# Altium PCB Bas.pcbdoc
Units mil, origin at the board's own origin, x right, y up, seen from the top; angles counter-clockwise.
Board outline 2425 x 2966 mil, 2 copper layers (Top Layer, Bottom Layer), stack 62.2 mil thick; 43 components, 38 nets, 146 pads, 58 vias.
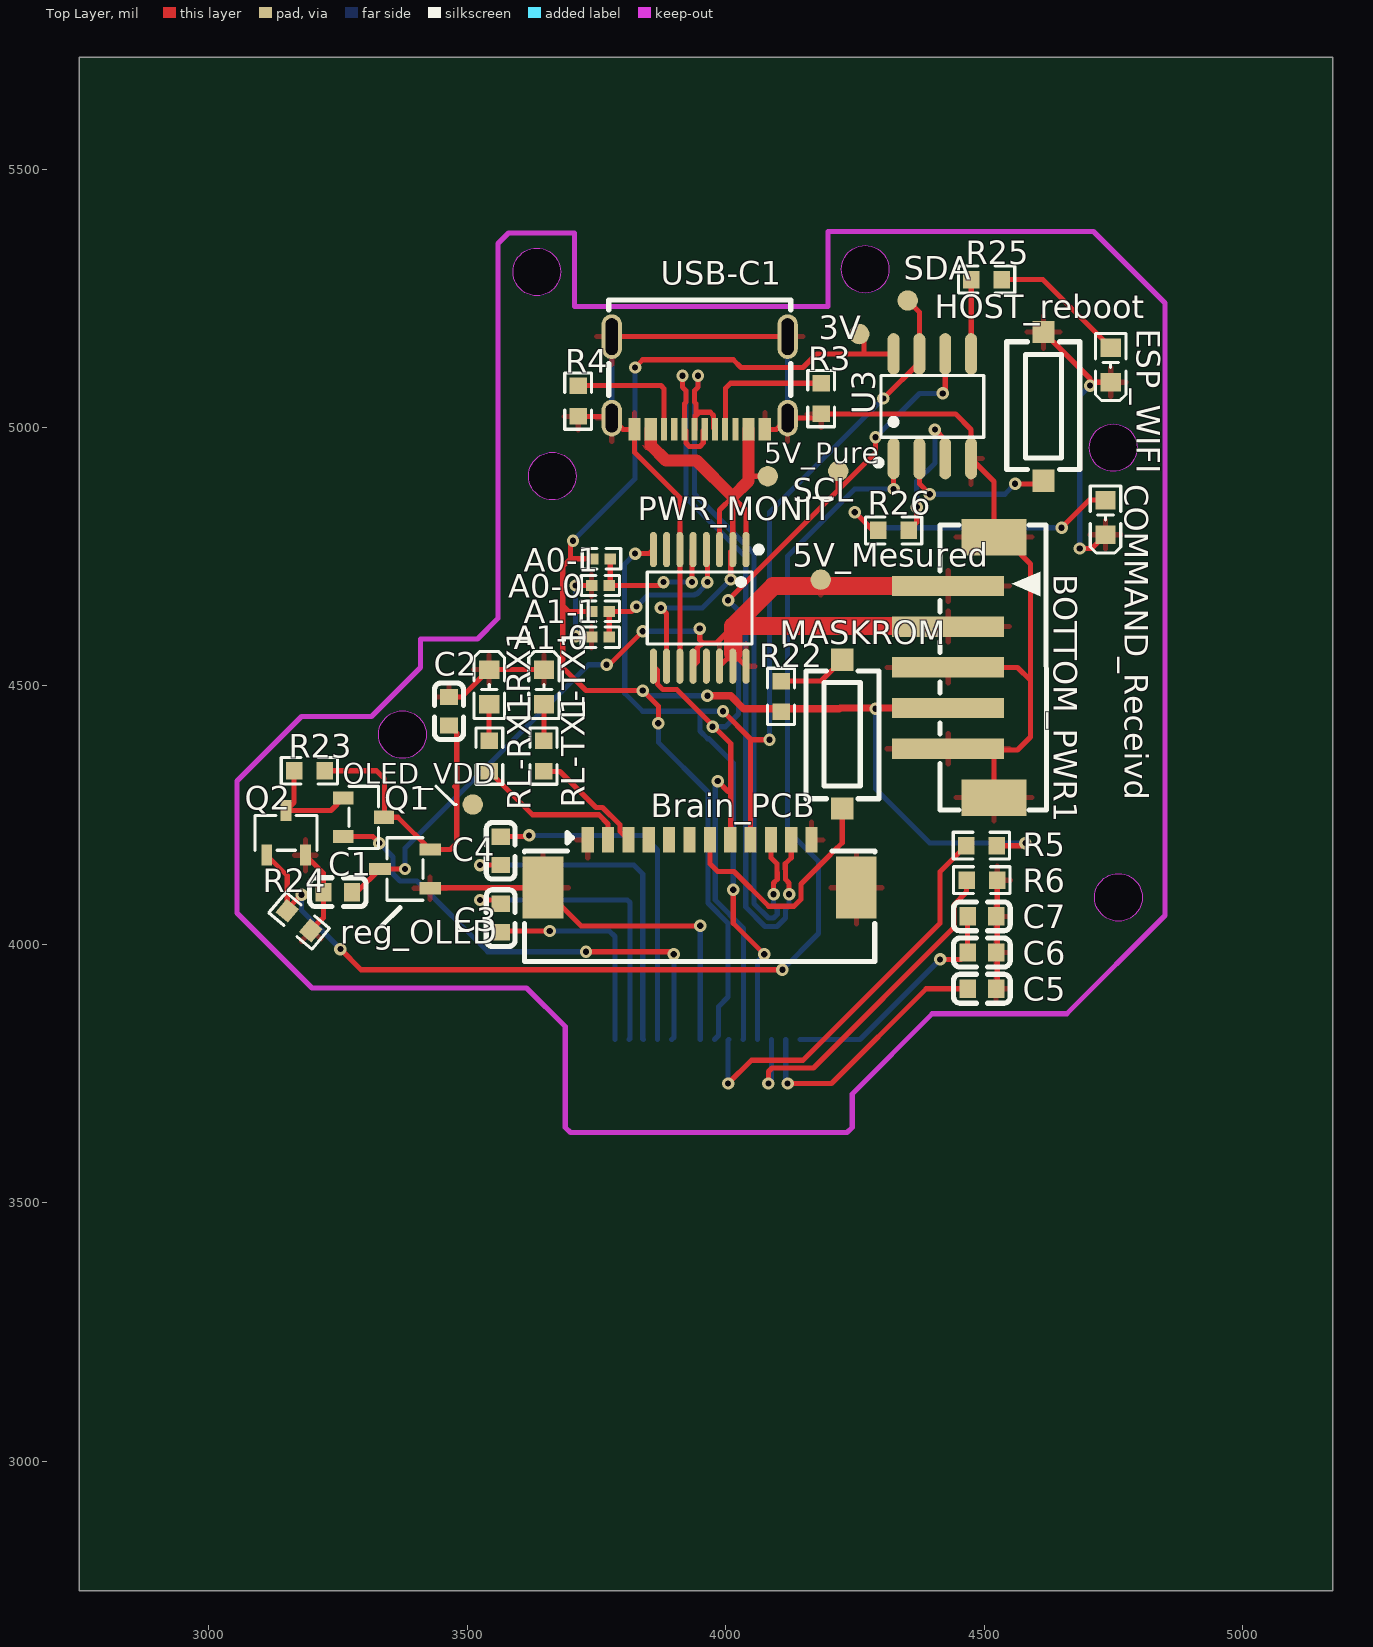
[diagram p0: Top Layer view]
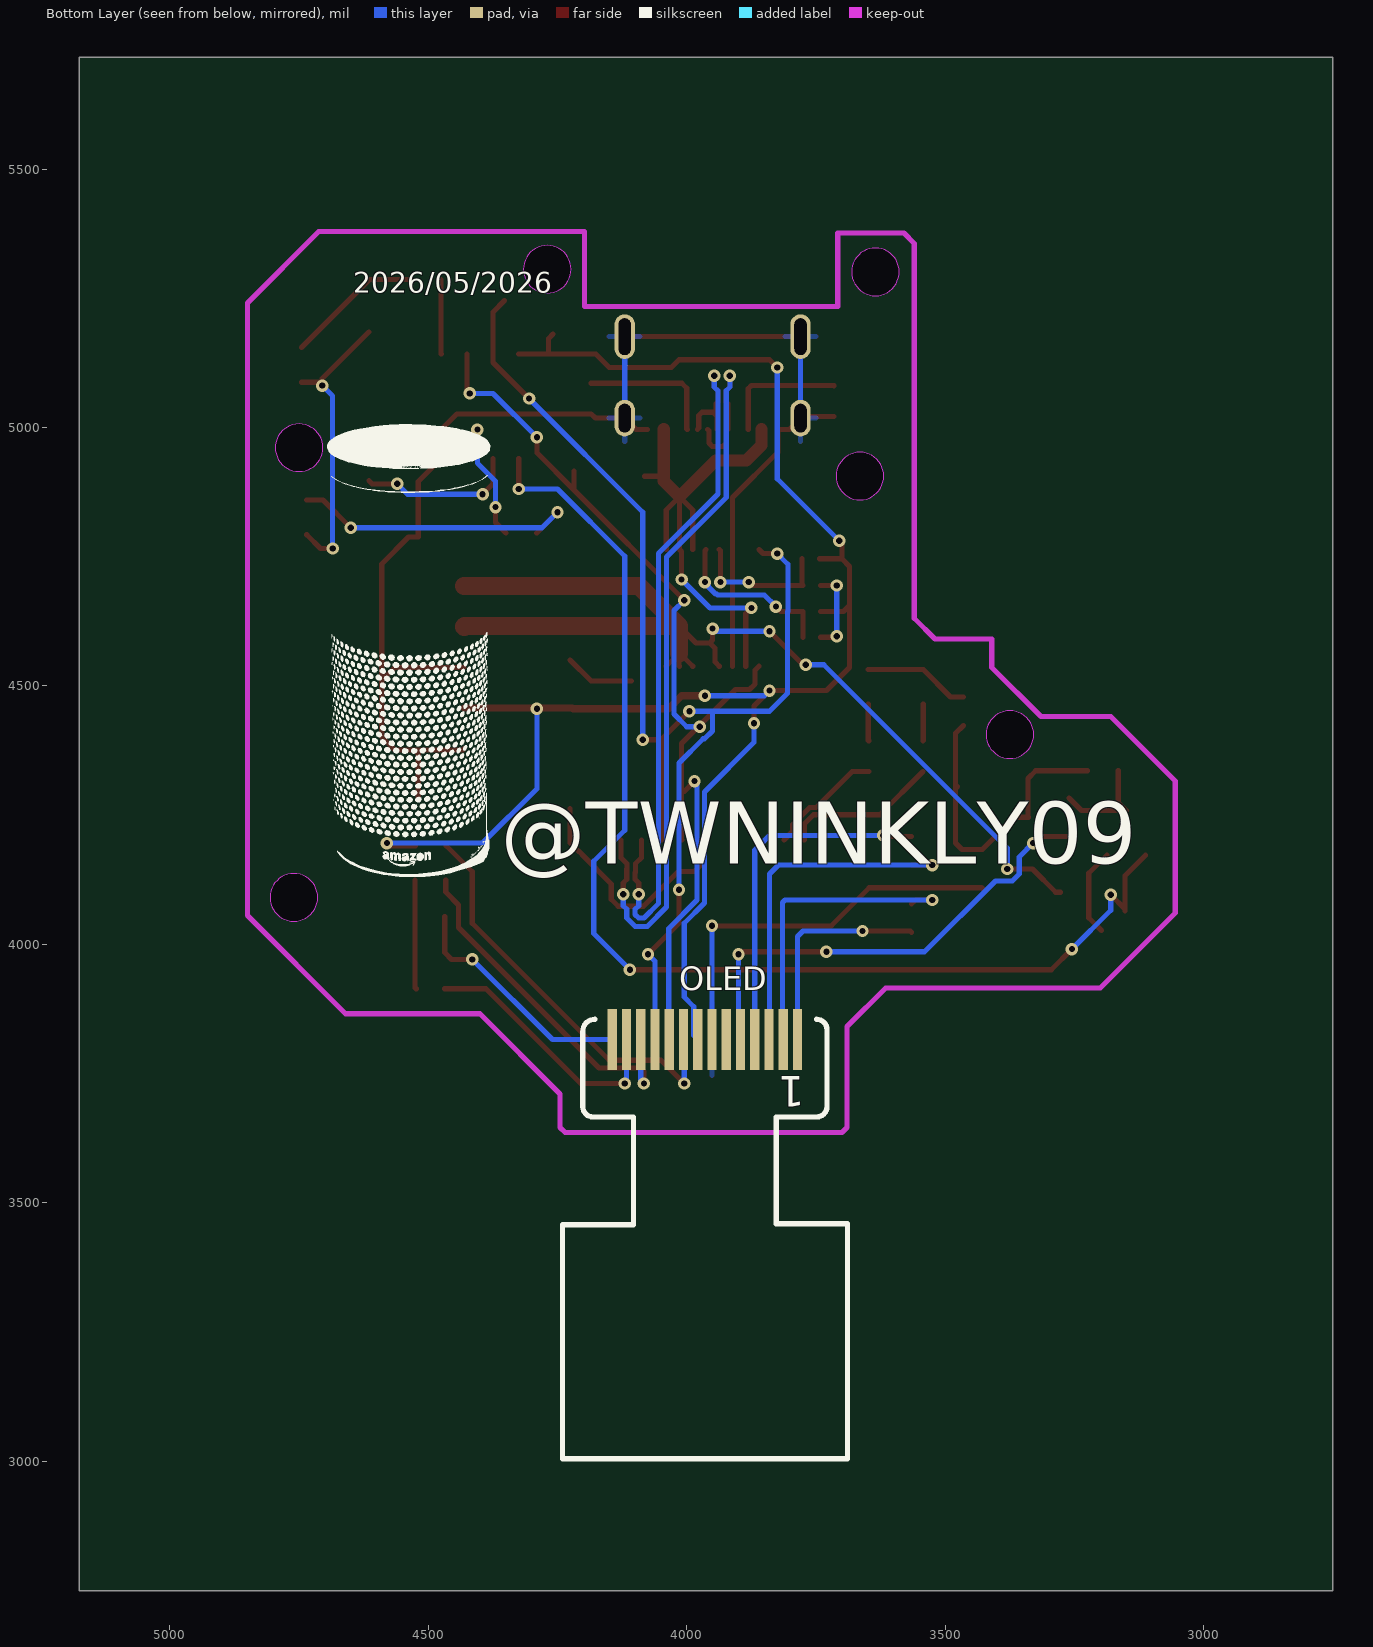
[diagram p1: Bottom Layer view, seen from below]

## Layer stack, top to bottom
Top Solder Mask Layer: solder mask 0.4, Dk 3.3
Top Layer: signal copper 1.4
Dielectric1: surface 59.4, FR4, Dk 4.5
Bottom Layer: signal copper 1.4
Bottom Solder Mask Layer: solder mask 0.4, Dk 3.3

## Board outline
5175,2750 2750,2750 2750,5716 5175,5716
cut-out: 3711.1,4906 3710.7,4900 3709.5,4894.1 3707.6,4888.4 3704.9,4883 3701.6,4878 3697.6,4873.4 3693.1,4869.5 3688,4866.1 3682.6,4863.4 3676.9,4861.5 3671,4860.3 3665,4859.9 3659,4860.3 3653.1,4861.5 3647.4,4863.4 3642,4866.1 3636.9,4869.5 3632.4,4873.4 3628.4,4878 3625.1,4883 3622.4,4888.4 3620.5,4894.1 3619.3,4900 3618.9,4906 3619.3,4912 3620.5,4918 3622.4,4923.7 3625.1,4929.1 3628.4,4934.1 3632.4,4938.6 3636.9,4942.6 3642,4945.9 3647.4,4948.6 3653.1,4950.5 3659,4951.7 3665,4952.1 3671,4951.7 3676.9,4950.5 3682.6,4948.6 3688,4945.9 3693.1,4942.6 3697.6,4938.6 3701.6,4934.1 3704.9,4929.1 3707.6,4923.7 3709.5,4918 3710.7,4912
cut-out: 3681.1,5301 3680.7,5295 3679.5,5289.1 3677.6,5283.4 3674.9,5278 3671.6,5273 3667.6,5268.4 3663.1,5264.5 3658,5261.1 3652.6,5258.4 3646.9,5256.5 3641,5255.3 3635,5254.9 3629,5255.3 3623.1,5256.5 3617.4,5258.4 3612,5261.1 3606.9,5264.5 3602.4,5268.4 3598.4,5273 3595.1,5278 3592.4,5283.4 3590.5,5289.1 3589.3,5295 3588.9,5301 3589.3,5307 3590.5,5313 3592.4,5318.7 3595.1,5324.1 3598.4,5329.1 3602.4,5333.6 3606.9,5337.6 3612,5340.9 3617.4,5343.6 3623.1,5345.5 3629,5346.7 3635,5347.1 3641,5346.7 3646.9,5345.5 3652.6,5343.6 3658,5340.9 3663.1,5337.6 3667.6,5333.6 3671.6,5329.1 3674.9,5324.1 3677.6,5318.7 3679.5,5313 3680.7,5307
cut-out: 4316.1,5306 4315.7,5300 4314.5,5294.1 4312.6,5288.4 4309.9,5283 4306.6,5278 4302.6,5273.4 4298.1,5269.5 4293,5266.1 4287.6,5263.4 4281.9,5261.5 4276,5260.3 4270,5259.9 4264,5260.3 4258.1,5261.5 4252.4,5263.4 4247,5266.1 4241.9,5269.5 4237.4,5273.4 4233.4,5278 4230.1,5283 4227.4,5288.4 4225.5,5294.1 4224.3,5300 4223.9,5306 4224.3,5312 4225.5,5318 4227.4,5323.7 4230.1,5329.1 4233.4,5334.1 4237.4,5338.6 4241.9,5342.6 4247,5345.9 4252.4,5348.6 4258.1,5350.5 4264,5351.7 4270,5352.1 4276,5351.7 4281.9,5350.5 4287.6,5348.6 4293,5345.9 4298.1,5342.6 4302.6,5338.6 4306.6,5334.1 4309.9,5329.1 4312.6,5323.7 4314.5,5318 4315.7,5312
cut-out: 4796.1,4961 4795.7,4955 4794.5,4949.1 4792.6,4943.4 4789.9,4938 4786.6,4933 4782.6,4928.4 4778.1,4924.5 4773,4921.1 4767.6,4918.4 4761.9,4916.5 4756,4915.3 4750,4914.9 4744,4915.3 4738.1,4916.5 4732.4,4918.4 4727,4921.1 4721.9,4924.5 4717.4,4928.4 4713.4,4933 4710.1,4938 4707.4,4943.4 4705.5,4949.1 4704.3,4955 4703.9,4961 4704.3,4967 4705.5,4973 4707.4,4978.7 4710.1,4984.1 4713.4,4989.1 4717.4,4993.6 4721.9,4997.6 4727,5000.9 4732.4,5003.6 4738.1,5005.5 4744,5006.7 4750,5007.1 4756,5006.7 4761.9,5005.5 4767.6,5003.6 4773,5000.9 4778.1,4997.6 4782.6,4993.6 4786.6,4989.1 4789.9,4984.1 4792.6,4978.7 4794.5,4973 4795.7,4967
cut-out: 4806.1,4091 4805.7,4085 4804.5,4079.1 4802.6,4073.4 4799.9,4068 4796.6,4063 4792.6,4058.4 4788.1,4054.5 4783,4051.1 4777.6,4048.4 4771.9,4046.5 4766,4045.3 4760,4044.9 4754,4045.3 4748.1,4046.5 4742.4,4048.4 4737,4051.1 4731.9,4054.5 4727.4,4058.4 4723.4,4063 4720.1,4068 4717.4,4073.4 4715.5,4079.1 4714.3,4085 4713.9,4091 4714.3,4097 4715.5,4103 4717.4,4108.7 4720.1,4114.1 4723.4,4119.1 4727.4,4123.6 4731.9,4127.6 4737,4130.9 4742.4,4133.6 4748.1,4135.5 4754,4136.7 4760,4137.1 4766,4136.7 4771.9,4135.5 4777.6,4133.6 4783,4130.9 4788.1,4127.6 4792.6,4123.6 4796.6,4119.1 4799.9,4114.1 4802.6,4108.7 4804.5,4103 4805.7,4097
cut-out: 3421.1,4406 3420.7,4400 3419.5,4394.1 3417.6,4388.4 3414.9,4383 3411.6,4378 3407.6,4373.4 3403.1,4369.5 3398,4366.1 3392.6,4363.4 3386.9,4361.5 3381,4360.3 3375,4359.9 3369,4360.3 3363.1,4361.5 3357.4,4363.4 3352,4366.1 3346.9,4369.5 3342.4,4373.4 3338.4,4378 3335.1,4383 3332.4,4388.4 3330.5,4394.1 3329.3,4400 3328.9,4406 3329.3,4412 3330.5,4418 3332.4,4423.7 3335.1,4429.1 3338.4,4434.1 3342.4,4438.6 3346.9,4442.6 3352,4445.9 3357.4,4448.6 3363.1,4450.5 3369,4451.7 3375,4452.1 3381,4451.7 3386.9,4450.5 3392.6,4448.6 3398,4445.9 3403.1,4442.6 3407.6,4438.6 3411.6,4434.1 3414.9,4429.1 3417.6,4423.7 3419.5,4418 3420.7,4412

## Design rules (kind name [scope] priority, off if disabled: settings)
BoardOutlineClearance copperThickness1oz [All] p0: genericclearance=10 ignorepadtopadclearanceinfootprint=FALSE except(0: Arc-SplitContinuation Track-SplitContinuation SMDPad-SplitContinuation THPad-SplitContinuation Via-SplitContinuation Fill-SplitContinuation Poly-SplitContinuation Region-SplitContinuation Text-SplitContinuation)
BoardOutlineClearance copperThickness2oz [All] p0: genericclearance=10 ignorepadtopadclearanceinfootprint=FALSE except(0: Arc-SplitContinuation Track-SplitContinuation SMDPad-SplitContinuation THPad-SplitContinuation Via-SplitContinuation Fill-SplitContinuation Poly-SplitContinuation Region-SplitContinuation Text-SplitContinuation)
BoardOutlineClearance Plane_innerPlane [All] p0: genericclearance=10 ignorepadtopadclearanceinfootprint=FALSE except(0: Arc-SplitContinuation Track-SplitContinuation SMDPad-SplitContinuation THPad-SplitContinuation Via-SplitContinuation Fill-SplitContinuation Poly-SplitContinuation Region-SplitContinuation Text-SplitContinuation)
BoardOutlineClearance Copper_copperRegion [All] p0: genericclearance=10 ignorepadtopadclearanceinfootprint=FALSE except(0: Arc-SplitContinuation Track-SplitContinuation SMDPad-SplitContinuation THPad-SplitContinuation Via-SplitContinuation Fill-SplitContinuation Poly-SplitContinuation Region-SplitContinuation Text-SplitContinuation)
BoardOutlineClearance otherClearance [All] p0: genericclearance=10 ignorepadtopadclearanceinfootprint=FALSE except(0: Arc-SplitContinuation Track-SplitContinuation SMDPad-SplitContinuation THPad-SplitContinuation Via-SplitContinuation Fill-SplitContinuation Poly-SplitContinuation Region-SplitContinuation Text-SplitContinuation)
Clearance copperThickness1oz [All] p1: gap=7 ignorepadtopadclearanceinfootprint=FALSE
Clearance copperThickness2oz [All] p1: gap=7 ignorepadtopadclearanceinfootprint=FALSE
Clearance Plane_innerPlane [All] p1: gap=7 ignorepadtopadclearanceinfootprint=FALSE
Clearance Copper_copperRegion [All] p1: gap=7 ignorepadtopadclearanceinfootprint=FALSE
Clearance otherClearance [All] p1: gap=7 ignorepadtopadclearanceinfootprint=FALSE
DiffPairsRouting differentialPair [All] p1: maxuncoupledlength=10 minlimit=6 maxlimit=Infinity mostfreqgap=6 toplayer_minwidth=5 toplayer_prefwidth=10 toplayer_maxwidth=100 bottomlayer_minwidth=5 bottomlayer_prefwidth=10 bottomlayer_maxwidth=100
PasteMaskExpansion pasteMaskExpansion [All] p1: expansion=0
PlaneConnect innerPlane [All] p1: planeconnectstyle=Relief reliefexpansion=20 reliefentries=4 reliefconductorwidth=10 reliefairgap=10
PolygonConnect copperRegion [All] p1: connectstyle=Relief reliefentries=4 reliefconductorwidth=10 polygonreliefangle="90 Angle" airgapwidth=10
RoutingVias viaSize [All] p1: viastyle="Through Hole" holewidth=12.0078 minholewidth=11.811 maxholewidth=248.0314 width=12.0078 minwidth=11.811 maxwidth=248.0314
SolderMaskExpansion solderMaskExpansion [IsVia] p1: useseparateexpansions=TRUE expansion=-1000 expansionbottom=-1000
SolderMaskExpansion solderMaskExpansion [All] p2: useseparateexpansions=TRUE expansion=2 expansionbottom=2
Width copperThickness1oz [All] p1: maxlimit=100 minlimit=5 preferedwidth=10
Width copperThickness2oz [All] p1: maxlimit=100 minlimit=8 preferedwidth=10

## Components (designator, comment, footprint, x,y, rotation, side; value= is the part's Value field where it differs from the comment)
3V "" Test-Point-0.5mm 4258.6,5180.7 r0 top
5V_Mesured "" Test-Point-0.5mm 4184.2,4705.7 r0 top
5V_Pure "" Test-Point-0.5mm 4081.7,4905.7 r0 top
A0-0 "0Ω" R0402#1 3758.1,4694.3 r180 top
A0-1 "0Ω" R0402#2 3760,4746 r180 top
A1-0 "0Ω" R0402#1 3758.1,4594.3 r180 top
A1-1 "0Ω" R0402#1 3758.1,4644.3 r180 top
BOTTOM_PWR1 "B5B-PH-SM4-TB(LF)(SN)" CONN-SMD_5P-P2.00_B6B-PH-SM4-TB-LF-SN 4475,4536 r90 top locked
Brain_PCB "FPC-1.0FX-12PWBH20" FPC-SMD_12P-P1.00_XUNPU_FPC-1.0FX-12PWBH20 3950,4156 r0 top locked
C1 "1uF" C0603#1 3250,4101 r0 top
C2 "1uF" C0603#2 3465,4451 r90 top
C3 "1uF" C0603#2 3565,4051 r90 top
C4 "1uF" C0603#3 3565,4181 r270 top
C5 "2.2uF" C0603#3 4495.9,3914.3 r0 top
C6 "4.7uF" C0603#2 4495.9,3984.3 r180 top
C7 "100nF" C0603#2 4495.9,4054.3 r180 top
COMMAND_Receivd "YLED0603O" LED0603-FD#1 4735,4826 r270 top
ESP_WIFI "YLED0603O" LED0603-FD#1 4745,5121 r270 top
HOST_reboot "HX 3x6x2.5A-2.5N" SW-SMD_HX-TS-1101-C-W 4615,5041 r90 top locked
L-RX1 "YLED0603O" LED0603-FD#2 3542.6,4498.1 r90 top
L-TX1 "YLED0603O" LED0603-FD#2 3648.8,4498.1 r90 top
MASKROM "HX 3x6x2.5A-2.5N" SW-SMD_HX-TS-1101-C-W 4225.7,4406.7 r270 top
OLED "X049-6432TSWPG02-H14" OLED-SMD_X049-6432TSWPG02-H14 3965,3816 r0 bottom locked
OLED_VDD "" Test-Point-0.5mm 3511.1,4270.7 r0 top
PWR_MONIT "INA260AIPW" TSSOP-16_L5.0-W4.4-P0.65-LS6.4-BL 3950,4651 r180 top locked
Q1 "FDN338P" SOT-23-3_L2.9-W1.3-P1.90-LS2.4-BR 3300,4246 r180 top
Q2 "FDN335N" SOT-23-3_L3.0-W1.7-P0.95-LS2.9-BR 3150,4216 r270 top
R3 "5.1kΩ" R0603_1 4185,5056 r90 top
R4 "5.1kΩ" R0603_1 3715,5051 r90 top
R5 "10kΩ" R0603#1 4495,4191 r180 top
R6 "560kΩ" R0603#2 4495.9,4124.3 r180 top
R22 "10kΩ" R0603#3 4107.4,4479.8 r270 top
R23 "47kΩ" R0603#1 3195,4336 r180 top
R24 "47kΩ" R0603#3 3175,4046 r320 top
R25 "330Ω" R0603#1 4505,5286 r0 top
R26 "330Ω" R0603#1 4325,4801 r180 top
reg_OLED "XC6206P402MR" SOT-23-3_L2.9-W1.6-P1.90-LS2.8-BR 3380,4146 r0 top
RL-RX1 "150Ω" R0603#2 3543.1,4364.3 r90 top
RL-TX1 "150Ω" R0603#2 3648.1,4364.3 r90 top
SCL "" Test-Point-0.5mm 4218,4915.7 r0 top
SDA "" Test-Point-0.5mm 4352.3,5245.7 r0 top
U3 "PCA9536D" SOIC-8_L4.9-W3.9-P1.27-LS6.0-BL 4400,5041 r0 top locked
USB-C1 "UC.01.51-11-0017,typec" TYPE-C-SMD_UC.01.51-11-0017 3950,5086 r180 top locked

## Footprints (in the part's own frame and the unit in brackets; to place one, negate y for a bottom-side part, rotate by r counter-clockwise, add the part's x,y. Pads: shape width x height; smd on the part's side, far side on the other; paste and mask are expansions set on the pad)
C0603#1 [mil]
  rect 31.5x35.4 smd: 1(-27.6,0) 2(27.6,0)
  silkscreen extent -55,-28 55,28
C0603#2 [mil]
  rect 31.5x35.4 smd: 1(-27.5,0) 2(27.6,0)
  silkscreen extent -55,-28 55,28
C0603#3 [mil]
  rect 31.5x35.4 smd: 1(-27.6,0) 2(27.5,0)
  silkscreen extent -55,-28 55,28
CONN-SMD_5P-P2.00_B6B-PH-SM4-TB-LF-SN [mil]
  rect 39.4x216.5 smd: 1(157.5,44.3) 2(78.8,44.3) 3(0,44.3) 4(-78.7,44.3) 5(-157.5,44.3)
  rect 70.9x126 smd: 6(252,-44.3) 7(-251.9,-44.3)
  silkscreen extent -276,-146 276,60
FPC-SMD_12P-P1.00_XUNPU_FPC-1.0FX-12PWBH20 [mil]
  rect 23.6x49.2 smd paste+0 mask+2: 1(-216.5,46.3) 2(-177.2,46.3) 3(-137.8,46.3) 4(-98.4,46.3) 5(-59.1,46.3) 6(-19.7,46.3) 7(19.7,46.3) 8(59.1,46.3) 9(98.4,46.3) 10(137.8,46.3) 11(177.2,46.3) 12(216.5,46.3)
  rect 78.7x120.1 smd paste+0 mask+2: 13(303.1,-46.2) 14(-303.1,-46.2)
  silkscreen extent -339,-189 339,60
LED0603-FD#1 [mil]
  rect 35.4x39.4 smd: 1(-33.5,0) 2(33.4,0)
  silkscreen extent -61,-30 69,30
LED0603-FD#2 [mil]
  rect 35.4x39.4 smd: 1(-33.4,0) 2(33.5,0)
  silkscreen extent -61,-30 69,30
OLED-SMD_X049-6432TSWPG02-H14 [mil]
  rect 17.7x118.1 smd: 1(-179.1,0) 2(-151.6,0) 3(-124,0) 4(-96.5,0) 5(-68.9,0) 6(-41.3,0) 7(-13.8,0) 8(13.8,0) 9(41.3,0) 10(68.9,0) 11(96.5,0) 12(124,0) 13(151.6,0) 14(179.1,0)
  silkscreen extent -276,-39 276,811
R0402#1 [mil]
  rect 22.3x21.3 smd paste-3937 mask+2: 1(-17,0) 2(17.1,0)
  silkscreen extent -37,-20 37,20
R0402#2 [mil]
  rect 22.3x21.3 smd paste-3937 mask+2: 1(-17,0) 2(17,0)
  silkscreen extent -37,-20 37,20
R0603#1 [mil]
  rect 31.8x34 smd paste-3937 mask+2: 1(-29.7,0) 2(29.7,0)
  silkscreen extent -54,-26 54,26
R0603#2 [mil]
  rect 31.8x34 smd paste-3937 mask+2: 1(-29.6,0) 2(29.7,0)
  silkscreen extent -54,-26 55,26
R0603#3 [mil]
  rect 31.8x34 smd paste-3937 mask+2: 1(-29.7,0) 2(29.6,0)
  silkscreen extent -55,-26 55,26
R0603_1 [mil]
  rect 31.8x34 smd paste-3937 mask+2: 1(-29.6,0) 2(29.7,0)
  silkscreen extent -54,-26 55,26
SOIC-8_L4.9-W3.9-P1.27-LS6.0-BL [mil]
  oval 23.1x80.5 smd: 1(-75,-101.2) 2(-25,-101.2) 3(25,-101.2) 4(75,-101.2) 5(75,101.2) 6(25,101.2) 7(-25,101.2) 8(-75,101.2)
  silkscreen extent -110,-115 100,60
SOT-23-3_L2.9-W1.3-P1.90-LS2.4-BR [mil]
  rect 39.4x25.6 smd: 1(39.4,-37.4) 2(39.4,37.4) 3(-39.4,0)
  silkscreen extent -29,-60 29,60
SOT-23-3_L2.9-W1.6-P1.90-LS2.8-BR [mil]
  rect 42.1x23.6 smd: 1(48.6,-37.4) 2(48.6,37.4) 3(-48.6,0)
  silkscreen extent -34,-60 34,60
SOT-23-3_L3.0-W1.7-P0.95-LS2.9-BR [mil]
  rect 40.8x20.9 smd: 1(43.3,-37.4) 2(43.3,37.4) 3(-43.4,0)
  silkscreen extent -34,-60 34,60
SW-SMD_HX-TS-1101-C-W [mil]
  rect 43.3x43.3 smd: 1(-143.7,0) 2(143.7,0)
  silkscreen extent -122,-70 125,71
Test-Point-0.5mm [mil]
  round 39.4 smd: 1(0,0)
TSSOP-16_L5.0-W4.4-P0.65-LS6.4-BL [mil]
  oval 13.5x68.2 smd: 1(-89.6,-112.8) 2(-64,-112.8) 3(-38.4,-112.8) 4(-12.8,-112.8) 5(12.8,-112.8) 6(38.4,-112.8) 7(64,-112.8) 8(89.6,-112.8) 9(89.6,112.8) 10(64,112.8) 11(38.4,112.8) 12(12.8,112.8) 13(-12.8,112.8) 14(-38.4,112.8) 15(-64,112.8) 16(-89.6,112.8)
  silkscreen extent -120,-119 101,70
TYPE-C-SMD_UC.01.51-11-0017 [mil]
  rect 23.6x44.1 smd paste-3937 mask+2: A1B12(-126,89.6) A4B9(-94.5,89.6) B1A12(126,89.6) B4A9(94.5,89.6)
  rect 11.8x44.1 smd paste-3937 mask+2: A5(-49.2,89.6) A6(-9.8,89.6) A7(9.8,89.6) A8(49.2,89.6) B5(68.9,89.6) B6(29.5,89.6) B7(-29.5,89.6) B8(-68.9,89.6)
  oval 39.4x86.6 hole 23.6 slot 70.9 at 90 deg: EH1(-170.1,-89.7) EH1(170.1,-89.7)
  oval 39.4x70.9 hole 23.6 slot 55.1 at 90 deg: EH1(-170.1,67.8) EH1(170.1,67.8)
  silkscreen extent -176,-161 176,24

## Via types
v1: diameter 24, hole 12, Top Layer to Bottom Layer, 58 vias

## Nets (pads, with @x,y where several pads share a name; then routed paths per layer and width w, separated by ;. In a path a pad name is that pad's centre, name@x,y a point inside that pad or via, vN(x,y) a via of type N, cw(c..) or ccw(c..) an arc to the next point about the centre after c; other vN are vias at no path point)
3V3: 3V.1 A0-1.2 A1-1.2 BOTTOM_PWR1.4 OLED.8 R5.1 R22.2 U3.8 | length 3386.7
  Top Layer w10: v1(3705,4781) 3700,4776 3700,4746 ; A1-1.2 3696.7,4644.3 3685,4656 ; A0-1.2 3700,4746 ; v1(3825,5116) 3840,5131 4015,5131 4030,5116 4150,5116 4176.2,5142.2 4267.5,5142.2 ; v1(3870,4428) 3870,4461 v1(3840,4491) 3730,4491 3685,4536 3685,4656 ; 3V.1 4267.5,5171.8 4267.5,5142.2 ; U3.8 4267.5,5142.2 ; R5.1 4575,4191 v1(4580,4196) ; 3685,4656 3685,4731 3700,4746
  Top Layer w13.8: v1(3965,4481) 4010,4481 4035,4456 4220,4456 4221.3,4457.3 BOTTOM_PWR1.4
  Bottom Layer w10: v1(3705,4781) 3825,4901 v1(3825,5116) ; v1(3840,4491) 3850,4481 v1(3965,4481) ; v1(3870,4428) 3870,4391 3966,4295 3966,4080.2 4005,4041.2 4005,3898.1 3986.5,3879.6 3986.5,3823.7 OLED.8 ; v1(4290,4456) 4290,4301 4395,4196 v1(4580,4196)
5V: 5V_Mesured.1 BOTTOM_PWR1.1 BOTTOM_PWR1.2 C1.2 PWR_MONIT.12 PWR_MONIT.14 PWR_MONIT.15 PWR_MONIT.16 reg_OLED.3 | length 2105.2
  Top Layer w10: C1.2 3286.4,4101 reg_OLED.3 v1(3380,4146) ; v1(3770,4541) 3775,4541 v1(3840,4606) ; PWR_MONIT.12 3945.1,4546.1 3945.1,4572.9 3955.4,4583.3 ; v1(3950,4611) 3950,4588.7 3955.4,4583.3 ; PWR_MONIT.14 PWR_MONIT.15@4015,4564.8 ; PWR_MONIT.15 4015,4539.2 4015,4562.8 PWR_MONIT.16 ; 4015,4616 3982.3,4583.3 3955.4,4583.3 ; 5V_Mesured.1@4195.3,4705.7 4207.5,4693.5 4215,4686
  Top Layer w35.4: PWR_MONIT.15@4015,4562.8 4015,4564.8 4015,4616 ; BOTTOM_PWR1.2 4429.4,4616 4015,4616 ; BOTTOM_PWR1.1 4207.5,4693.5 4092.5,4693.5 4015,4616
  Bottom Layer w10: v1(3380,4146) 3380,4186 3735,4541 v1(3770,4541) ; v1(3840,4606) 3945,4606 v1(3950,4611)
5V_IN: 5V_Pure.1 PWR_MONIT.1 PWR_MONIT.2 PWR_MONIT.3 PWR_MONIT.10 USB-C1.A4B9 USB-C1.B4A9 | length 1073.7
  Top Layer w10: v1(3875,4651) 3886,4640 PWR_MONIT.10 ; PWR_MONIT.3 3988.4,4840.4 4014,4866 ; v1(4010,4706) 4010,4759.9 PWR_MONIT.2 4014,4866 ; PWR_MONIT.1 4039.6,4840.4 4014,4866 ; 4044.5,4906.7 4045.5,4905.7 5V_Pure.1
  Top Layer w23.6: USB-C1.B4A9 3855.5,4965.5 3885,4936 3944,4936 4014,4866 4044.5,4896.5 4044.5,4906.7 USB-C1.A4B9
  Bottom Layer w10: v1(3875,4651) 3955,4651 v1(4010,4706)
$1N269: L-TX1.1 RL-TX1.2 | length 71
  Top Layer w10: RL-TX1.2 3648.8,4394.7 L-TX1.1
$1N274: L-RX1.1 RL-RX1.2 | length 70.9
  Top Layer w10: L-RX1.1 3542.6,4394.4 RL-RX1.2
$1N1066: R4.2 USB-C1.B5 | length 247.3
  Top Layer w10: R4.2 3715.3,5081 3875,5081 3881.1,5074.9 USB-C1.B5
$1N1071: R3.2 USB-C1.A5 | length 269
  Top Layer w10: USB-C1.A5 4000,4997.1 4000,5076 4009.7,5085.7 R3.2
$1N5114: A0-0.1 A0-1.1 PWR_MONIT.5 | length 278.8
  Top Layer w10: A0-1.1 3777,4696.3 A0-0.1 3873.3,4694.3 v1(3880,4701) ; v1(3935,4701) 3935,4761.6 PWR_MONIT.5
  Bottom Layer w10: v1(3880,4701) v1(3935,4701)
$1N6382: C3.1 OLED.1 | length 425.6
  Top Layer w10: C3.1 3567.6,4026 v1(3660,4026)
  Bottom Layer w10: v1(3660,4026) 3775,4026 3785.9,4015.2 OLED.1
$1N6420: C3.2 OLED.2 | length 600.8
  Top Layer w10: v1(3525,4086) 3557.6,4086 C3.2
  Bottom Layer w10: v1(3525,4086) 3810,4086 3815,4081 3815,3817.6 OLED.2
$1N6458: C4.1 OLED.4 | length 682.8
  Top Layer w10: C4.1 3617.6,4208.6 v1(3620,4211)
  Bottom Layer w10: v1(3620,4211) 3840,4211 3868.5,4182.5 OLED.4
$1N6496: C4.2 OLED.3 | length 682.7
  Top Layer w10: v1(3525,4153.5) C4.2
  Bottom Layer w10: v1(3525,4153.5) 3822.6,4153.5 3840,4136 3840,3817 OLED.3
$1N6597: OLED.9 R5.2 | length 794.8
  Top Layer w10: v1(4005,3731) 4050,3776 4150,3776 4415,4041 4415,4140.7 R5.2
  Bottom Layer w10: v1(4005,3731) 4005,3814.7 OLED.9
$1N6719: OLED.12 R6.2 | length 686.5
  Top Layer w10: v1(4082.9,3731) 4082.9,3754 4090,3761 4170,3761 4441.6,4032.6 4441.6,4076.6 4466.2,4101.2 R6.2
  Bottom Layer w10: v1(4082.9,3731) 4089,3737.1 OLED.12
$1N6952: C6.2 C7.2 OLED.14 | length 463.9
  Top Layer w10: v1(4415,3971) 4455,3971 C6.2 C7.2
  Bottom Layer w10: OLED.14 4260,3816 v1(4415,3971)
$1N19302: A1-0.1 A1-1.1 PWR_MONIT.4 | length 328.6
  Top Layer w10: A1-0.1 A1-1.1 3818.3,4644.3 v1(3827.5,4653.5) ; PWR_MONIT.4 3965,4761.6 v1(3965,4701)
  Bottom Layer w10: v1(3827.5,4653.5) 3850,4676 3940,4676 3942,4678 3944.5,4678 3958,4691.5 3958,4694 v1(3965,4701)
$1N20402: OLED.5 Q1.2 | length 919.3
  Top Layer w10: Q1.2 3317.4,4208.6 v1(3330,4196) ; v1(3730,3986) 3895,3986 v1(3900,3981)
  Bottom Layer w10: v1(3330,4196) 3357,4169 3357,4136.5 3370.5,4123 3403,4123 3540,3986 v1(3730,3986) ; OLED.5 3900,3819.9 v1(3900,3981)
$1N20576: Q1.1 Q2.3 R23.2 | length 203.5
  Top Layer w10: R23.2 3165.3,4274.7 Q2.3 3236.6,4259.4 Q1.1
$1N20760: MASKROM.1 R22.1 | length 135.2
  Top Layer w10: R22.1 4184.8,4509.5 MASKROM.1
$1N23802: COMMAND_Receivd.1 R26.2 | length 576.5
  Top Layer w10: v1(4250,4836) 4250.3,4836 R26.2@4290.3,4796 ; v1(4650,4806) 4703.5,4859.5 COMMAND_Receivd.1
  Bottom Layer w10: v1(4250,4836) 4280,4806 v1(4650,4806)
$1N23841: ESP_WIFI.1 R25.2 | length 264.8
  Top Layer w10: R25.2 4613.5,5286 ESP_WIFI.1
$1N23909: R26.1 U3.3 | length 287.4
  Top Layer w10: R26.1@4349.7,4796 4370,4816.4 v1(4370,4846) ; v1(4405,4996) 4425,4976 U3.3
  Bottom Layer w10: v1(4370,4846) 4370,4896 4405,4931 v1(4405,4996)
$1N23915: R25.1 U3.5 | length 143.9
  Top Layer w10: U3.5 4475.3,5142.5 R25.1
D+: Brain_PCB.11 USB-C1.A6 USB-C1.B6 | length 1542
  Top Layer w10: v1(3916.7,5100) 3916.7,5078 3923.7,5071 3923.7,5049.3 3920.5,5046 USB-C1.B6 3923.3,4993.6 3923.3,4969.8 3929.7,4963.3 3950.6,4963.3 3957,4969.8 3957,4993.6 USB-C1.A6 ; v1(4123,4097) 4123,4119 4116,4126 4116,4145.5 4115.5,4146 4115.5,4156 4127.2,4167.7 Brain_PCB.11
  Bottom Layer w10: v1(3916.7,5100) 3916.7,5078 3923.7,5071 3923.7,4864.7 4039,4749.4 4039,4072.2 4076.3,4034.9 4099.6,4034.9 4116,4051.4 4116,4068 4123,4075 v1(4123,4097)
D-: Brain_PCB.10 USB-C1.A7 USB-C1.B7 | length 1461.1
  Top Layer w10: USB-C1.A7@3941,4996.4 3941,5000.2 3941,5023 ; v1(3946.7,5100) 3946.7,5078 3939.7,5071 3939.7,5049.3 3943,5046 3943,5023 3949.4,5029.4 3970.3,5029.4 3976.7,5023 3976.7,4999.1 USB-C1.B7 ; Brain_PCB.10 4087.8,4167.7 4099.5,4156 4099.5,4139.4 4100,4138.8 4100,4126 4093,4119 v1(4093,4097)
  Bottom Layer w10: v1(3946.7,5100) 3946.7,5078 3939.7,5071 3939.7,4871.3 4055,4756 4055,4078.9 4082.9,4050.9 4092.9,4050.9 4100,4058 4100,4068 4093,4075 v1(4093,4097)
GND: A0-0.2 A1-0.2 BOTTOM_PWR1.3 BOTTOM_PWR1.5 BOTTOM_PWR1.6 BOTTOM_PWR1.7 Brain_PCB.1 Brain_PCB.12 Brain_PCB.13 Brain_PCB.14 C1.1 C2.2 C5.2 C6.1 C7.1 COMMAND_Receivd.2 ESP_WIFI.2 HOST_reboot.2 L-RX1.2 L-TX1.2 OLED.7 PWR_MONIT.6 PWR_MONIT.11 Q2.2 R3.1 R4.1 R6.1 R24.2 reg_OLED.1 U3.4 USB-C1.A1B12 USB-C1.B1A12 USB-C1.EH1 | length 4871.2
  Top Layer w10: Q2.2 3222.4,4137.6 C1.1 3222.4,4051.7 R24.2 ; reg_OLED.1 3429.8,4109.8 Brain_PCB.14 3720.6,4036 v1(3951.2,4036) ; C2.2 3489.6,4478.6 L-RX1.2 L-TX1.2 ; v1(3710,4596) 3711.7,4594.3 A1-0.2 ; v1(3710,4694.3) A0-0.2 ; R4.1 3776.8,5021.4 3779.9,5018.2 3801.8,4996.4 USB-C1.B1A12 3824,4952 3911.6,4864.4 PWR_MONIT.6 PWR_MONIT.11 ; USB-C1.EH1@3779.9,5175.7 USB-C1.EH1@4120.1,5175.7 ; USB-C1.A1B12 4098.2,4996.4 4120.1,5018.2 4176.8,5018.2 R3.1 4444.7,5026.4 4475,4996 U3.4 4519.3,4895.6 BOTTOM_PWR1.6 4538,4788 4590,4736 4590,4511 ; BOTTOM_PWR1.5 4433.2,4376 BOTTOM_PWR1.5@4525.4,4376 ; BOTTOM_PWR1.3 4565,4536 4590,4511 ; BOTTOM_PWR1.7 4519.3,4369.9 BOTTOM_PWR1.5@4525.4,4376 ; C5.2 4525.5,3916.4 R6.1 ; HOST_reboot.2 4705,5094.7 v1(4705,5081) 4711.5,5087.6 ESP_WIFI.2 ; v1(4685,4766) 4708.5,4766 COMMAND_Receivd.2 ; BOTTOM_PWR1.5@4525.4,4376 4565,4376 4590,4401 4590,4511
  Bottom Layer w10: v1(3710,4596) v1(3710,4694.3) ; USB-C1.EH1@3779.9,5018.2 USB-C1.EH1@3779.9,5175.7 ; OLED.7 v1(3951.2,4036) ; USB-C1.EH1@4120.1,5018.2 USB-C1.EH1@4120.1,5175.7 ; v1(4685,4766) 4685,5061 v1(4705,5081)
LED_RX: Brain_PCB.2 RL-RX1.1 | length 302.7
  Top Layer w10: RL-RX1.1 3626.7,4251 3755,4251 3772.8,4233.2 Brain_PCB.2
LED_TX: Brain_PCB.3 RL-TX1.1 | length 226.3
  Top Layer w10: RL-TX1.1 3679.8,4334.7 3749.4,4265 3762,4265 3795.6,4231.4 3795.6,4218.9 Brain_PCB.3
MASKROM_BTN: Brain_PCB.7 MASKROM.2 | length 470.8
  Top Layer w10: Brain_PCB.7 3970,4202 3970,4156 3985,4141 4016.5,4141 4083.5,4074 4132.5,4074 4146,4087.5 4146,4117 4202.8,4173.8 4202.8,4174.4 4209.2,4180.8 4209.8,4180.8 4225.7,4196.7 MASKROM.2
OLED_RST: Q2.1 R24.1 U3.1 | length 2342.3
  Top Layer w10: Q2.1 3152.3,4133 R24.1@3152.3,4068.3 ; R24.1 R24.1@3152.3,4068.3 ; v1(3180,4096) R24.1@3152.3,4068.3 ; v1(3255,3991) 3295,3951 v1(4110,3951) ; v1(4325,4881) U3.1
  Bottom Layer w10: v1(3180,4096) 3180,4066 v1(3255,3991) ; v1(4110,3951) 4180,4021 4180,4161 4120,4221 4120,4751 4250,4881 v1(4325,4881)
PHONE_DET: Brain_PCB.6
PHONE_L: Brain_PCB.4
PHONE_R: Brain_PCB.5
SCL: Brain_PCB.8 OLED.10 PWR_MONIT.9 SCL.1 U3.6 | length 1974.4
  Top Layer w10: PWR_MONIT.9 3868.3,4530.3 3868.3,4503.5 3878.7,4493.1 3905.5,4493.1 4010,4388.6 4010,4296 ; v1(3985,4316) 4005,4296 4010,4296 ; v1(4005,4666) 4218,4879 ; Brain_PCB.8 4010,4203.2 4010,4296 ; SCL.1 4218,4879 ; v1(4290,4981) 4290,4951 4218,4879 ; v1(4420,5066) 4425,5071 U3.6
  Bottom Layer w10: v1(3975,4421) 4000,4421 4025,4446 4025,4646 v1(4005,4666) ; v1(3985,4316) 3980,4311 3980,4086 4035,4031 4035,3817.1 OLED.10 ; v1(4290,4981) 4375,5066 v1(4420,5066)
SDA: Brain_PCB.9 OLED.11 PWR_MONIT.8 SDA.1 U3.7 | length 2502.8
  Top Layer w10: v1(3825,4756) 3852.6,4756 PWR_MONIT.8 ; v1(3995,4451) 4048.4,4397.6 ; v1(4015,4106) 4015,4041 v1(4075,3981) ; Brain_PCB.9 4048.4,4397.6 ; v1(4085,4396) 4050,4396 4048.4,4397.6 ; v1(4305,5056) 4375,5126 U3.7 4375,5223 SDA.1
  Bottom Layer w10: v1(3825,4756) 3804.5,4735.5 3804.5,4644 3805,4643.5 3805,4486 3840,4451 3950.5,4451 ; v1(3995,4451) 3950.5,4451 ; v1(4015,4106) 4015,4351 3968,4398 3965.5,4398 3950.5,4413 3950.5,4451 ; OLED.11 4061.5,3967.5 v1(4075,3981) ; v1(4085,4396) 4085,4836 v1(4305,5056)
SOFT_RST: HOST_reboot.1 U3.2 | length 308
  Top Layer w10: U3.2 4375,4891 v1(4395,4871) ; v1(4560,4891) 4608.7,4891 HOST_reboot.1
  Bottom Layer w10: v1(4395,4871) 4540,4871 v1(4560,4891)
VBAT: C2.1 OLED_VDD.1 Q1.3 R23.1 reg_OLED.2 | length 607.7
  Top Layer w10: R23.1 3325,4336 3340,4321 3340,4246.7 Q1.3 3366,4246 reg_OLED.2 3467.4,4183.4 3480,4196 3480,4301.8 ; C2.1 3480,4408.5 3480,4301.8 ; 3476.1,4305.7 3480,4301.8
VCOM: C5.1 OLED.13 | length 510.6
  Top Layer w10: v1(4120,3731) 4205,3731 4388.3,3914.3 C5.1
  Bottom Layer w10: OLED.13 4116.6,3734.4 v1(4120,3731)
pads on no net: OLED.6 PWR_MONIT.7 PWR_MONIT.13 USB-C1.A8 USB-C1.B8

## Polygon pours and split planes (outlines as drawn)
5V on Top Layer (solid, remove dead copper, pour order 2): 4078,4720.8 3975,4617.8 3975,4501 3990,4486 4045,4486 4070,4511 4070,4576 4560,4576 4575,4591 4575,4712.3 4553.7,4733.6 4090,4733.6 4078,4721.5
5V_IN on Top Layer (solid, remove dead copper, pour order 4): 3845.6,4956.5 3840,4966 3849.6,4956.5
5V_IN on Top Layer (solid, remove dead copper, pour order 6): 3887.9,4911 3843.4,4956.5 4064.2,4956.5 4064.5,4911 4064.2,4900 4064.2,4722.9 4050,4716 3980,4716 3975,4721 3975,4851 3915,4911
GND on Top Layer (solid, remove dead copper, pour order 8): 3005,5466 3005,3581 4920,3581 4920,5466
GND on Bottom Layer (solid, remove dead copper, pour order 8): 3000,5426 3000,3591 4925,3591 4925,5426

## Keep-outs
Board Outline Layer:
  region: 3711.1,4906 3710.7,4900 3709.5,4894.1 3707.6,4888.4 3704.9,4883 3701.6,4878 3697.6,4873.4 3693.1,4869.5 3688,4866.1 3682.6,4863.4 3676.9,4861.5 3671,4860.3 3665,4859.9 3659,4860.3 3653.1,4861.5 3647.4,4863.4 3642,4866.1 3636.9,4869.5 3632.4,4873.4 3628.4,4878 3625.1,4883 3622.4,4888.4 3620.5,4894.1 3619.3,4900 3618.9,4906 3619.3,4912 3620.5,4918 3622.4,4923.7 3625.1,4929.1 3628.4,4934.1 3632.4,4938.6 3636.9,4942.6 3642,4945.9 3647.4,4948.6 3653.1,4950.5 3659,4951.7 3665,4952.1 3671,4951.7 3676.9,4950.5 3682.6,4948.6 3688,4945.9 3693.1,4942.6 3697.6,4938.6 3701.6,4934.1 3704.9,4929.1 3707.6,4923.7 3709.5,4918 3710.7,4912
  region: 3711.1,4906 3710.7,4900 3709.5,4894.1 3707.6,4888.4 3704.9,4883 3701.6,4878 3697.6,4873.4 3693.1,4869.5 3688,4866.1 3682.6,4863.4 3676.9,4861.5 3671,4860.3 3665,4859.9 3659,4860.3 3653.1,4861.5 3647.4,4863.4 3642,4866.1 3636.9,4869.5 3632.4,4873.4 3628.4,4878 3625.1,4883 3622.4,4888.4 3620.5,4894.1 3619.3,4900 3618.9,4906 3619.3,4912 3620.5,4918 3622.4,4923.7 3625.1,4929.1 3628.4,4934.1 3632.4,4938.6 3636.9,4942.6 3642,4945.9 3647.4,4948.6 3653.1,4950.5 3659,4951.7 3665,4952.1 3671,4951.7 3676.9,4950.5 3682.6,4948.6 3688,4945.9 3693.1,4942.6 3697.6,4938.6 3701.6,4934.1 3704.9,4929.1 3707.6,4923.7 3709.5,4918 3710.7,4912
  region: 3681.1,5301 3680.7,5295 3679.5,5289.1 3677.6,5283.4 3674.9,5278 3671.6,5273 3667.6,5268.4 3663.1,5264.5 3658,5261.1 3652.6,5258.4 3646.9,5256.5 3641,5255.3 3635,5254.9 3629,5255.3 3623.1,5256.5 3617.4,5258.4 3612,5261.1 3606.9,5264.5 3602.4,5268.4 3598.4,5273 3595.1,5278 3592.4,5283.4 3590.5,5289.1 3589.3,5295 3588.9,5301 3589.3,5307 3590.5,5313 3592.4,5318.7 3595.1,5324.1 3598.4,5329.1 3602.4,5333.6 3606.9,5337.6 3612,5340.9 3617.4,5343.6 3623.1,5345.5 3629,5346.7 3635,5347.1 3641,5346.7 3646.9,5345.5 3652.6,5343.6 3658,5340.9 3663.1,5337.6 3667.6,5333.6 3671.6,5329.1 3674.9,5324.1 3677.6,5318.7 3679.5,5313 3680.7,5307
  region: 3681.1,5301 3680.7,5295 3679.5,5289.1 3677.6,5283.4 3674.9,5278 3671.6,5273 3667.6,5268.4 3663.1,5264.5 3658,5261.1 3652.6,5258.4 3646.9,5256.5 3641,5255.3 3635,5254.9 3629,5255.3 3623.1,5256.5 3617.4,5258.4 3612,5261.1 3606.9,5264.5 3602.4,5268.4 3598.4,5273 3595.1,5278 3592.4,5283.4 3590.5,5289.1 3589.3,5295 3588.9,5301 3589.3,5307 3590.5,5313 3592.4,5318.7 3595.1,5324.1 3598.4,5329.1 3602.4,5333.6 3606.9,5337.6 3612,5340.9 3617.4,5343.6 3623.1,5345.5 3629,5346.7 3635,5347.1 3641,5346.7 3646.9,5345.5 3652.6,5343.6 3658,5340.9 3663.1,5337.6 3667.6,5333.6 3671.6,5329.1 3674.9,5324.1 3677.6,5318.7 3679.5,5313 3680.7,5307
  region: 4316.1,5306 4315.7,5300 4314.5,5294.1 4312.6,5288.4 4309.9,5283 4306.6,5278 4302.6,5273.4 4298.1,5269.5 4293,5266.1 4287.6,5263.4 4281.9,5261.5 4276,5260.3 4270,5259.9 4264,5260.3 4258.1,5261.5 4252.4,5263.4 4247,5266.1 4241.9,5269.5 4237.4,5273.4 4233.4,5278 4230.1,5283 4227.4,5288.4 4225.5,5294.1 4224.3,5300 4223.9,5306 4224.3,5312 4225.5,5318 4227.4,5323.7 4230.1,5329.1 4233.4,5334.1 4237.4,5338.6 4241.9,5342.6 4247,5345.9 4252.4,5348.6 4258.1,5350.5 4264,5351.7 4270,5352.1 4276,5351.7 4281.9,5350.5 4287.6,5348.6 4293,5345.9 4298.1,5342.6 4302.6,5338.6 4306.6,5334.1 4309.9,5329.1 4312.6,5323.7 4314.5,5318 4315.7,5312
  region: 4316.1,5306 4315.7,5300 4314.5,5294.1 4312.6,5288.4 4309.9,5283 4306.6,5278 4302.6,5273.4 4298.1,5269.5 4293,5266.1 4287.6,5263.4 4281.9,5261.5 4276,5260.3 4270,5259.9 4264,5260.3 4258.1,5261.5 4252.4,5263.4 4247,5266.1 4241.9,5269.5 4237.4,5273.4 4233.4,5278 4230.1,5283 4227.4,5288.4 4225.5,5294.1 4224.3,5300 4223.9,5306 4224.3,5312 4225.5,5318 4227.4,5323.7 4230.1,5329.1 4233.4,5334.1 4237.4,5338.6 4241.9,5342.6 4247,5345.9 4252.4,5348.6 4258.1,5350.5 4264,5351.7 4270,5352.1 4276,5351.7 4281.9,5350.5 4287.6,5348.6 4293,5345.9 4298.1,5342.6 4302.6,5338.6 4306.6,5334.1 4309.9,5329.1 4312.6,5323.7 4314.5,5318 4315.7,5312
  region: 4796.1,4961 4795.7,4955 4794.5,4949.1 4792.6,4943.4 4789.9,4938 4786.6,4933 4782.6,4928.4 4778.1,4924.5 4773,4921.1 4767.6,4918.4 4761.9,4916.5 4756,4915.3 4750,4914.9 4744,4915.3 4738.1,4916.5 4732.4,4918.4 4727,4921.1 4721.9,4924.5 4717.4,4928.4 4713.4,4933 4710.1,4938 4707.4,4943.4 4705.5,4949.1 4704.3,4955 4703.9,4961 4704.3,4967 4705.5,4973 4707.4,4978.7 4710.1,4984.1 4713.4,4989.1 4717.4,4993.6 4721.9,4997.6 4727,5000.9 4732.4,5003.6 4738.1,5005.5 4744,5006.7 4750,5007.1 4756,5006.7 4761.9,5005.5 4767.6,5003.6 4773,5000.9 4778.1,4997.6 4782.6,4993.6 4786.6,4989.1 4789.9,4984.1 4792.6,4978.7 4794.5,4973 4795.7,4967
  region: 4796.1,4961 4795.7,4955 4794.5,4949.1 4792.6,4943.4 4789.9,4938 4786.6,4933 4782.6,4928.4 4778.1,4924.5 4773,4921.1 4767.6,4918.4 4761.9,4916.5 4756,4915.3 4750,4914.9 4744,4915.3 4738.1,4916.5 4732.4,4918.4 4727,4921.1 4721.9,4924.5 4717.4,4928.4 4713.4,4933 4710.1,4938 4707.4,4943.4 4705.5,4949.1 4704.3,4955 4703.9,4961 4704.3,4967 4705.5,4973 4707.4,4978.7 4710.1,4984.1 4713.4,4989.1 4717.4,4993.6 4721.9,4997.6 4727,5000.9 4732.4,5003.6 4738.1,5005.5 4744,5006.7 4750,5007.1 4756,5006.7 4761.9,5005.5 4767.6,5003.6 4773,5000.9 4778.1,4997.6 4782.6,4993.6 4786.6,4989.1 4789.9,4984.1 4792.6,4978.7 4794.5,4973 4795.7,4967
  region: 4806.1,4091 4805.7,4085 4804.5,4079.1 4802.6,4073.4 4799.9,4068 4796.6,4063 4792.6,4058.4 4788.1,4054.5 4783,4051.1 4777.6,4048.4 4771.9,4046.5 4766,4045.3 4760,4044.9 4754,4045.3 4748.1,4046.5 4742.4,4048.4 4737,4051.1 4731.9,4054.5 4727.4,4058.4 4723.4,4063 4720.1,4068 4717.4,4073.4 4715.5,4079.1 4714.3,4085 4713.9,4091 4714.3,4097 4715.5,4103 4717.4,4108.7 4720.1,4114.1 4723.4,4119.1 4727.4,4123.6 4731.9,4127.6 4737,4130.9 4742.4,4133.6 4748.1,4135.5 4754,4136.7 4760,4137.1 4766,4136.7 4771.9,4135.5 4777.6,4133.6 4783,4130.9 4788.1,4127.6 4792.6,4123.6 4796.6,4119.1 4799.9,4114.1 4802.6,4108.7 4804.5,4103 4805.7,4097
  region: 4806.1,4091 4805.7,4085 4804.5,4079.1 4802.6,4073.4 4799.9,4068 4796.6,4063 4792.6,4058.4 4788.1,4054.5 4783,4051.1 4777.6,4048.4 4771.9,4046.5 4766,4045.3 4760,4044.9 4754,4045.3 4748.1,4046.5 4742.4,4048.4 4737,4051.1 4731.9,4054.5 4727.4,4058.4 4723.4,4063 4720.1,4068 4717.4,4073.4 4715.5,4079.1 4714.3,4085 4713.9,4091 4714.3,4097 4715.5,4103 4717.4,4108.7 4720.1,4114.1 4723.4,4119.1 4727.4,4123.6 4731.9,4127.6 4737,4130.9 4742.4,4133.6 4748.1,4135.5 4754,4136.7 4760,4137.1 4766,4136.7 4771.9,4135.5 4777.6,4133.6 4783,4130.9 4788.1,4127.6 4792.6,4123.6 4796.6,4119.1 4799.9,4114.1 4802.6,4108.7 4804.5,4103 4805.7,4097
  region: 3421.1,4406 3420.7,4400 3419.5,4394.1 3417.6,4388.4 3414.9,4383 3411.6,4378 3407.6,4373.4 3403.1,4369.5 3398,4366.1 3392.6,4363.4 3386.9,4361.5 3381,4360.3 3375,4359.9 3369,4360.3 3363.1,4361.5 3357.4,4363.4 3352,4366.1 3346.9,4369.5 3342.4,4373.4 3338.4,4378 3335.1,4383 3332.4,4388.4 3330.5,4394.1 3329.3,4400 3328.9,4406 3329.3,4412 3330.5,4418 3332.4,4423.7 3335.1,4429.1 3338.4,4434.1 3342.4,4438.6 3346.9,4442.6 3352,4445.9 3357.4,4448.6 3363.1,4450.5 3369,4451.7 3375,4452.1 3381,4451.7 3386.9,4450.5 3392.6,4448.6 3398,4445.9 3403.1,4442.6 3407.6,4438.6 3411.6,4434.1 3414.9,4429.1 3417.6,4423.7 3419.5,4418 3420.7,4412
  region: 3421.1,4406 3420.7,4400 3419.5,4394.1 3417.6,4388.4 3414.9,4383 3411.6,4378 3407.6,4373.4 3403.1,4369.5 3398,4366.1 3392.6,4363.4 3386.9,4361.5 3381,4360.3 3375,4359.9 3369,4360.3 3363.1,4361.5 3357.4,4363.4 3352,4366.1 3346.9,4369.5 3342.4,4373.4 3338.4,4378 3335.1,4383 3332.4,4388.4 3330.5,4394.1 3329.3,4400 3328.9,4406 3329.3,4412 3330.5,4418 3332.4,4423.7 3335.1,4429.1 3338.4,4434.1 3342.4,4438.6 3346.9,4442.6 3352,4445.9 3357.4,4448.6 3363.1,4450.5 3369,4451.7 3375,4452.1 3381,4451.7 3386.9,4450.5 3392.6,4448.6 3398,4445.9 3403.1,4442.6 3407.6,4438.6 3411.6,4434.1 3414.9,4429.1 3417.6,4423.7 3419.5,4418 3420.7,4412
  lines w0.1: 3328.9,4406 3329.3,4400 3330.5,4394.1 3332.4,4388.4 3335.1,4383 3338.4,4378 3342.4,4373.4 3346.9,4369.5 3352,4366.1 3357.4,4363.4 3363.1,4361.5 3369,4360.3 3375,4359.9 3381,4360.3 3386.9,4361.5 3392.6,4363.4 3398,4366.1 3403.1,4369.5 3407.6,4373.4 3411.6,4378 3414.9,4383 3417.6,4388.4 3419.5,4394.1 3420.7,4400 3421.1,4406 3420.7,4412 3419.5,4418 3417.6,4423.7 3414.9,4429.1 3411.6,4434.1 3407.6,4438.6 3403.1,4442.6 3398,4445.9 3392.6,4448.6 3386.9,4450.5 3381,4451.7 3375,4452.1 3369,4451.7 3363.1,4450.5 3357.4,4448.6 3352,4445.9 3346.9,4442.6 3342.4,4438.6 3338.4,4434.1 3335.1,4429.1 3332.4,4423.7 3330.5,4418 3329.3,4412 3328.9,4406 ; 3588.9,5301 3589.3,5295 3590.5,5289.1 3592.4,5283.4 3595.1,5278 3598.4,5273 3602.4,5268.4 3606.9,5264.5 3612,5261.1 3617.4,5258.4 3623.1,5256.5 3629,5255.3 3635,5254.9 3641,5255.3 3646.9,5256.5 3652.6,5258.4 3658,5261.1 3663.1,5264.5 3667.6,5268.4 3671.6,5273 3674.9,5278 3677.6,5283.4 3679.5,5289.1 3680.7,5295 3681.1,5301 3680.7,5307 3679.5,5313 3677.6,5318.7 3674.9,5324.1 3671.6,5329.1 3667.6,5333.6 3663.1,5337.6 3658,5340.9 3652.6,5343.6 3646.9,5345.5 3641,5346.7 3635,5347.1 3629,5346.7 3623.1,5345.5 3617.4,5343.6 3612,5340.9 3606.9,5337.6 3602.4,5333.6 3598.4,5329.1 3595.1,5324.1 3592.4,5318.7 3590.5,5313 3589.3,5307 3588.9,5301 ; 3618.9,4906 3619.3,4900 3620.5,4894.1 3622.4,4888.4 3625.1,4883 3628.4,4878 3632.4,4873.4 3636.9,4869.5 3642,4866.1 3647.4,4863.4 3653.1,4861.5 3659,4860.3 3665,4859.9 3671,4860.3 3676.9,4861.5 3682.6,4863.4 3688,4866.1 3693.1,4869.5 3697.6,4873.4 3701.6,4878 3704.9,4883 3707.6,4888.4 3709.5,4894.1 3710.7,4900 3711.1,4906 3710.7,4912 3709.5,4918 3707.6,4923.7 3704.9,4929.1 3701.6,4934.1 3697.6,4938.6 3693.1,4942.6 3688,4945.9 3682.6,4948.6 3676.9,4950.5 3671,4951.7 3665,4952.1 3659,4951.7 3653.1,4950.5 3647.4,4948.6 3642,4945.9 3636.9,4942.6 3632.4,4938.6 3628.4,4934.1 3625.1,4929.1 3622.4,4923.7 3620.5,4918 3619.3,4912 3618.9,4906 ; 4223.9,5306 4224.3,5300 4225.5,5294.1 4227.4,5288.4 4230.1,5283 4233.4,5278 4237.4,5273.4 4241.9,5269.5 4247,5266.1 4252.4,5263.4 4258.1,5261.5 4264,5260.3 4270,5259.9 4276,5260.3 4281.9,5261.5 4287.6,5263.4 4293,5266.1 4298.1,5269.5 4302.6,5273.4 4306.6,5278 4309.9,5283 4312.6,5288.4 4314.5,5294.1 4315.7,5300 4316.1,5306 4315.7,5312 4314.5,5318 4312.6,5323.7 4309.9,5329.1 4306.6,5334.1 4302.6,5338.6 4298.1,5342.6 4293,5345.9 4287.6,5348.6 4281.9,5350.5 4276,5351.7 4270,5352.1 4264,5351.7 4258.1,5350.5 4252.4,5348.6 4247,5345.9 4241.9,5342.6 4237.4,5338.6 4233.4,5334.1 4230.1,5329.1 4227.4,5323.7 4225.5,5318 4224.3,5312 4223.9,5306 ; 4703.9,4961 4704.3,4955 4705.5,4949.1 4707.4,4943.4 4710.1,4938 4713.4,4933 4717.4,4928.4 4721.9,4924.5 4727,4921.1 4732.4,4918.4 4738.1,4916.5 4744,4915.3 4750,4914.9 4756,4915.3 4761.9,4916.5 4767.6,4918.4 4773,4921.1 4778.1,4924.5 4782.6,4928.4 4786.6,4933 4789.9,4938 4792.6,4943.4 4794.5,4949.1 4795.7,4955 4796.1,4961 4795.7,4967 4794.5,4973 4792.6,4978.7 4789.9,4984.1 4786.6,4989.1 4782.6,4993.6 4778.1,4997.6 4773,5000.9 4767.6,5003.6 4761.9,5005.5 4756,5006.7 4750,5007.1 4744,5006.7 4738.1,5005.5 4732.4,5003.6 4727,5000.9 4721.9,4997.6 4717.4,4993.6 4713.4,4989.1 4710.1,4984.1 4707.4,4978.7 4705.5,4973 4704.3,4967 4703.9,4961 ; 4713.9,4091 4714.3,4085 4715.5,4079.1 4717.4,4073.4 4720.1,4068 4723.4,4063 4727.4,4058.4 4731.9,4054.5 4737,4051.1 4742.4,4048.4 4748.1,4046.5 4754,4045.3 4760,4044.9 4766,4045.3 4771.9,4046.5 4777.6,4048.4 4783,4051.1 4788.1,4054.5 4792.6,4058.4 4796.6,4063 4799.9,4068 4802.6,4073.4 4804.5,4079.1 4805.7,4085 4806.1,4091 4805.7,4097 4804.5,4103 4802.6,4108.7 4799.9,4114.1 4796.6,4119.1 4792.6,4123.6 4788.1,4127.6 4783,4130.9 4777.6,4133.6 4771.9,4135.5 4766,4136.7 4760,4137.1 4754,4136.7 4748.1,4135.5 4742.4,4133.6 4737,4130.9 4731.9,4127.6 4727.4,4123.6 4723.4,4119.1 4720.1,4114.1 4717.4,4108.7 4715.5,4103 4714.3,4097 4713.9,4091
  lines w10: 3580,5376 3560,5356 3560,4631 3520,4591 3410,4591 3410,4536 3315,4441 3180,4441 3055,4316 3055,4061 3200,3916 3615,3916 3690,3841 3690,3646 3700,3636 4235,3636 4245,3646 4245,3711 4400,3866 4660,3866 4850,4056 4850,5241 4711.8,5379.3 4198.1,5379.3 4198.1,5324.7 4198.1,5234.3 3708.1,5234.3 3708.1,5326.9 3708.1,5376.3 3580,5376.3

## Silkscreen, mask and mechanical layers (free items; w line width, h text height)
Top Silkscreen Layer:
  lines w5.9: 3440,4306 3475,4271 3480,4271
  lines w10: 3335,4036 3370,4071
Bottom Silkscreen Layer:
  drawing of 693 lines, arcs and shapes, not listed
  text "2026/05/2026" at 4645,5261 h39.4
  text "@TWNINKLY09" at 4360,4156.3 h120
Mechanical Layer:
  drawing of 288 lines, arcs and shapes, not listed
